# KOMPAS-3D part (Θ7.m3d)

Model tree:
1. Эскиз:1
2. Операция выдавливания:1
     Расстояние 1 = 2
3. Скругление:1
     Радиус = 2
4. Эскиз:2
5. Вырезать элемент выдавливания:1
     Расстояние 1 = 10
